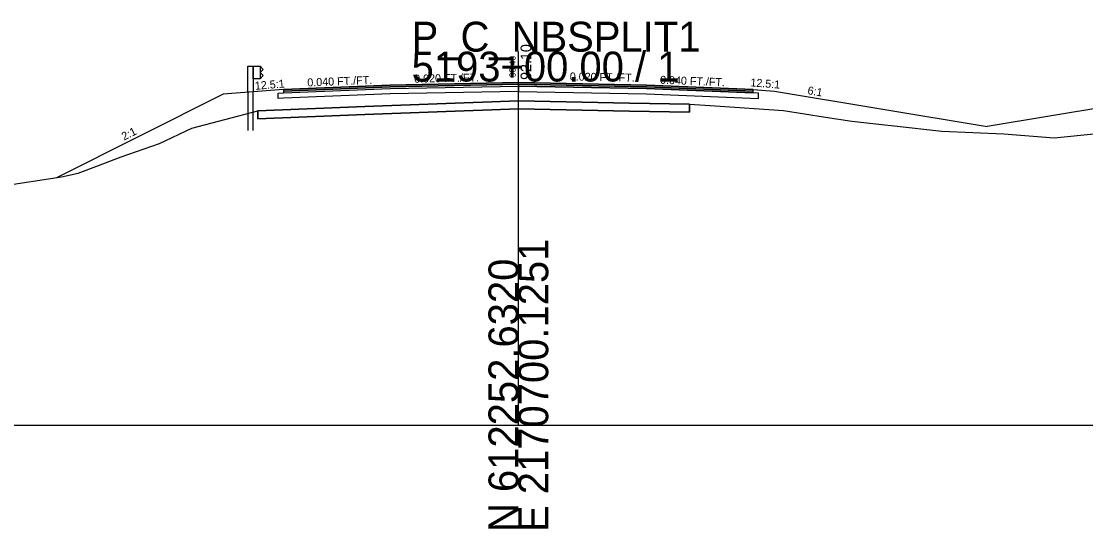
# Model space of a CAD drawing. Extents: x -26 to 1303, y -3010 to 12038.
# Drawn here: x 103.4 to 203.1, y 9990.3 to 10037.8 of the extents above; entities that cross this region are included whole.
import ezdxf

# ---------------------------------------------------------------- set-up
doc = ezdxf.new("R2010")
doc.units = 0
for name, color, linetype in [('RD_GPK_XS_Cell', 7, 'Continuous'), ('RD_PD_Final_TrvlWay', 7, 'Continuous'), ('RD_XS_Base', 7, 'Continuous'), ('RD_XS_ExGround', 7, 'Continuous'), ('RD_XS_ExPaveRet', 7, 'Continuous'), ('RD_XS_GR', 7, 'Continuous'), ('RD_XS_Greenside', 7, 'Continuous'), ('RD_XS_Pave', 7, 'Continuous'), ('RD_XS_PaveOvlay_CP', 7, 'Continuous'), ('RD_XS_TieSlope', 7, 'Continuous'), ('RD_XS_TX_Elev_EX', 7, 'Continuous'), ('RD_XS_TX_Elev_PR', 7, 'Continuous'), ('RD_XS_TX_ShdSlope', 7, 'Continuous'), ('RD_XS_TX_Slope', 7, 'Continuous')]:
    doc.layers.add(name, color=color, linetype=linetype)

msp = doc.modelspace()

# ---------------------------------------------------------------- linework, layer by layer
at = {"layer": 'RD_GPK_XS_Cell'}
for p, q in [((150, 10000), (150, 10035)), ((0, 10000), (150, 10000)), ((150, 10000), (300, 10000))]:
    msp.add_line(p, q, dxfattribs=at)
at = {"layer": 'RD_PD_Final_TrvlWay'}
for p, q in [((125.162, 10031.23), (124.662, 10031.19)), ((124.662, 10031.19), (124.662, 10027.624)), ((125.162, 10027.624), (125.162, 10031.23))]:
    msp.add_line(p, q, dxfattribs=at)
at = {"layer": 'RD_XS_Base'}
for p, q in [((150, 10031.779), (150, 10031.938)), ((150, 10031.938), (150, 10031.279)), ((127.5, 10031.119), (128, 10031.139)), ((127.5, 10030.619), (127.5, 10031.119)), ((127.5, 10031.119), (127.5, 10031.119)), ((128, 10031.139), (138, 10031.538)), ((128, 10031.139), (128, 10031.139)), ((138, 10031.038), (128, 10030.639)), ((138, 10031.538), (150, 10031.779)), ((138, 10031.538), (138, 10031.538)), ((150, 10031.279), (138, 10031.038)), ((138, 10031.038), (138, 10031.038)), ((150, 10031.779), (150, 10031.279)), ((162, 10031.538), (150, 10031.779)), ((150, 10031.779), (150, 10031.779)), ((150, 10031.279), (150, 10031.279)), ((150, 10031.279), (150, 10031.279)), ((150, 10031.279), (162, 10031.038)), ((172, 10031.139), (162, 10031.538)), ((162, 10031.038), (172.5, 10030.619)), ((164, 10031.458), (164, 10031.458)), ((164, 10030.958), (164, 10030.958)), ((172.5, 10031.119), (172, 10031.139)), ((172, 10031.139), (172, 10031.139)), ((172.5, 10030.619), (172.5, 10031.119)), ((172.5, 10031.119), (172.5, 10031.119)), ((128, 10030.639), (127.5, 10030.619)), ((127.5, 10030.619), (127.5, 10030.619)), ((127.5, 10030.619), (127.5, 10030.619)), ((128, 10030.639), (128, 10030.639)), ((172.5, 10030.619), (172.5, 10030.619)), ((172.5, 10030.619), (172.5, 10030.619))]:
    msp.add_line(p, q, dxfattribs=at)
at = {"layer": 'RD_XS_ExGround'}
msp.add_lwpolyline([(101.489, 10022.384), (107.203, 10023.266), (108.772, 10023.622), (110.679, 10024.34), (112.8, 10025.152), (116.381, 10026.402), (119.422, 10027.83), (125.583, 10029.464), (135.604, 10029.868), (149.998, 10030.402), (160.416, 10030.186), (166.025, 10030.067), (168.418, 10029.915), (174.84, 10029.489), (178.766, 10028.875), (181.231, 10028.493), (184.045, 10028.184), (185.188, 10028.057), (189.662, 10027.563), (195.461, 10027.303), (200.182, 10026.931), (211.342, 10028.036)], dxfattribs=at)
at = {"layer": 'RD_XS_ExPaveRet'}
for p, q in [((135.604, 10029.868), (125.583, 10029.464)), ((149.998, 10030.402), (135.604, 10029.868))]:
    msp.add_line(p, q, dxfattribs=at)
for points in [[(166.025, 10030.067), (166.025, 10030.067), (166.025, 10029.317), (166.025, 10029.317), (166.025, 10029.317), (160.416, 10029.436), (160.416, 10029.436), (149.998, 10029.652), (149.998, 10029.652), (149.998, 10029.652), (135.604, 10029.118), (135.604, 10029.118), (125.583, 10028.714), (125.583, 10028.714), (125.583, 10029.464), (135.604, 10029.868), (135.604, 10029.868), (149.998, 10030.402), (149.998, 10030.402), (149.998, 10030.402), (160.416, 10030.186), (160.416, 10030.186), (166.025, 10030.067), (166.025, 10030.067), (166.025, 10030.067)], [(125.583, 10029.464), (125.583, 10028.714), (135.604, 10029.118), (149.998, 10029.652), (160.416, 10029.436), (166.025, 10029.317), (166.025, 10030.067), (160.416, 10030.186), (149.998, 10030.402)]]:
    msp.add_lwpolyline(points, dxfattribs=at)
at = {"layer": 'RD_XS_GR'}
for points in [[(125.162, 10033.624), (125.162, 10031.23), (124.662, 10031.19), (124.662, 10033.624), (124.912, 10033.624), (125.162, 10033.624)], [(125.829, 10033.624), (125.829, 10032.458), (125.162, 10032.458), (125.162, 10033.624), (125.829, 10033.624)], [(126.1, 10033.333), (125.829, 10033.624), (125.829, 10032.458), (125.829, 10032.458), (125.829, 10032.458), (126.1, 10032.749), (126.1, 10032.749), (125.829, 10033.041), (125.829, 10033.041), (126.1, 10033.333), (126.1, 10033.333)]]:
    msp.add_lwpolyline(points, dxfattribs=at)
at = {"layer": 'RD_XS_Greenside'}
for p, q in [((122.35, 10031.005), (106.725, 10023.192)), ((174, 10031.297), (193.9, 10027.98)), ((211.91, 10030.982), (193.9, 10027.98))]:
    msp.add_line(p, q, dxfattribs=at)
at = {"layer": 'RD_XS_Pave'}
for p, q in [((138, 10031.857), (128, 10031.457)), ((150, 10032.097), (138, 10031.857)), ((150, 10031.938), (138, 10031.697)), ((138, 10031.697), (150, 10031.938)), ((138, 10031.857), (138, 10031.857)), ((162, 10031.857), (150, 10032.097)), ((150, 10031.779), (150, 10031.938)), ((150, 10031.938), (162, 10031.697)), ((162, 10031.697), (150, 10031.938)), ((150, 10031.938), (150, 10031.779)), ((172, 10031.457), (162, 10031.857)), ((138, 10031.697), (128, 10031.298)), ((128, 10031.298), (138, 10031.697)), ((128, 10031.139), (138, 10031.538)), ((128, 10031.457), (128, 10031.457)), ((128, 10031.457), (128, 10031.298)), ((128, 10031.298), (128, 10031.298)), ((128, 10031.298), (128, 10031.139)), ((128, 10031.298), (128, 10031.298)), ((128, 10031.298), (128, 10031.298)), ((128, 10031.139), (128, 10031.139)), ((128, 10031.139), (128, 10031.139)), ((138, 10031.538), (150, 10031.779)), ((138, 10031.697), (138, 10031.697)), ((138, 10031.697), (138, 10031.697)), ((138, 10031.538), (138, 10031.538)), ((150, 10031.779), (150, 10031.779)), ((150, 10031.779), (150, 10031.779)), ((150, 10031.779), (162, 10031.538)), ((162, 10031.697), (172, 10031.298)), ((172, 10031.298), (162, 10031.697)), ((162, 10031.538), (172, 10031.139)), ((164, 10031.777), (164, 10031.777)), ((164, 10031.617), (164, 10031.617)), ((164, 10031.617), (164, 10031.617)), ((164, 10031.458), (164, 10031.458)), ((172, 10031.298), (172, 10031.457)), ((172, 10031.457), (172, 10031.457)), ((172, 10031.298), (172, 10031.298)), ((172, 10031.298), (172, 10031.298)), ((172, 10031.139), (172, 10031.298)), ((172, 10031.298), (172, 10031.298)), ((172, 10031.139), (172, 10031.139)), ((172, 10031.139), (172, 10031.139))]:
    msp.add_line(p, q, dxfattribs=at)
at = {"layer": 'RD_XS_PaveOvlay_CP'}
for p, q in [((128, 10031.457), (138, 10031.857)), ((138, 10031.857), (150, 10032.097)), ((150, 10032.097), (162, 10031.857)), ((162, 10031.857), (172, 10031.457))]:
    msp.add_line(p, q, dxfattribs=at)
at = {"layer": 'RD_XS_TieSlope'}
for p, q in [((128, 10031.457), (122.35, 10031.005)), ((172, 10031.457), (174, 10031.297))]:
    msp.add_line(p, q, dxfattribs=at)

# ---------------------------------------------------------------- texts
at = {"layer": 'RD_GPK_XS_Cell'}
for s, p in [('P_C_NBSPLIT1', (140, 10035)), ('5193+00.00 / 1', (140, 10032.2))]:
    msp.add_text(s, height=2.8, dxfattribs=at).set_placement(p)
for s, p in [('E 2170700.1251', (152.8, 9990)), ('N 612252.6320', (150, 9990))]:
    msp.add_text(s, height=2.8, rotation=90, dxfattribs=at).set_placement(p)
at = {"layer": 'RD_XS_TX_Elev_EX'}
msp.add_text('90.40', height=0.6, rotation=90, dxfattribs=at).set_placement((149.744, 10032.598))
at = {"layer": 'RD_XS_TX_Elev_PR'}
msp.add_text('92.10', height=1, rotation=90, dxfattribs=at).set_placement((151.207, 10032.351))
at = {"layer": 'RD_XS_TX_ShdSlope'}
for rotation, p in [(4.57392, (125.35, 10031.42)), (355.42608, (171.711, 10031.751))]:
    msp.add_text('12.5:1', height=0.75, rotation=rotation, dxfattribs=at).set_placement(p)
at = {"layer": 'RD_XS_TX_Slope'}
for s, rotation, p in [('0.020 FT./FT.', 1.14576, (140.248, 10032.087)), ('0.020 FT./FT.', 358.85424, (154.807, 10032.302)), ('0.040 FT./FT.', 2.29061, (130.247, 10031.732)), ('0.040 FT./FT.', 357.70939, (163.262, 10031.992)), ('6:1', 350.53768, (177.044, 10031.022)), ('2:1', 26.56505, (113.065, 10026.661))]:
    msp.add_text(s, height=0.75, rotation=rotation, dxfattribs=at).set_placement(p)

doc.saveas('drawing.dxf')
